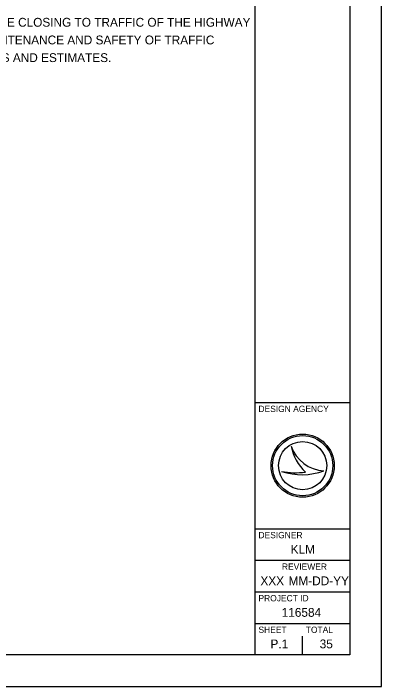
# Model space of a CAD drawing. Extents: x 0 to 34, y 0 to 22.
# Drawn here: x 28.17 to 34, y 0 to 10.67 of the extents above; entities that cross this region are included whole.
import ezdxf

# ---------------------------------------------------------------- set-up
doc = ezdxf.new("R2010")
doc.units = 0
for name, color, linetype in [('GM_X_County', 7, 'Continuous'), ('GM_X_Minor_Lake_Text', 7, 'Continuous'), ('GM_X_Minor_River_Text', 7, 'Continuous')]:
    doc.layers.add(name, color=color, linetype=linetype)

msp = doc.modelspace()

# ---------------------------------------------------------------- linework, layer by layer
at = {"layer": 'GM_X_County'}
msp.add_lwpolyline([(0, 0), (34, 0), (34, 22), (0, 22)], close=True, dxfattribs=at)
at = {"layer": 'GM_X_Minor_Lake_Text'}
for p, q in [((32.567, 3.81), (32.567, 3.81)), ((32.75, 3.5), (32.75, 3.5)), ((33.087, 3.419), (33.087, 3.419)), ((32.417, 3.41), (32.417, 3.41)), ((32.75, 0.5), (32.75, 0.8)), ((32.375, 0.675), (32.375, 0.675))]:
    msp.add_line(p, q, dxfattribs=at)
for radius in [0.5, 0.477, 0.477, 0.382]:
    msp.add_circle((32.75, 3.5), radius, dxfattribs=at)
for centre, radius, start, end in [((33.116, 3.998), 0.58, 198.9257, 198.9319), ((33.347, 3.97), 0.796, 191.6379, 191.6421), ((33.116, 3.998), 0.58, 198.9319, 267.1657), ((33.347, 3.97), 0.796, 191.6421, 226.0947), ((32.739, 4.37), 1.013, 251.4576, 290.0832), ((32.648, 4.654), 1.266, 259.4964, 259.4995), ((32.739, 4.37), 1.013, 251.4527, 251.4576), ((32.648, 4.654), 1.266, 259.4995, 276.6672)]:
    msp.add_arc(centre, radius, start, end, dxfattribs=at)
at = {"layer": 'GM_X_Minor_River_Text'}
for p, q in [((32, 0.5), (32, 21.5)), ((32, 4.5), (33.5, 4.5)), ((32, 2.5), (33.5, 2.5)), ((32, 2), (33.5, 2)), ((32, 1.5), (33.5, 1.5)), ((32, 1), (33.5, 1))]:
    msp.add_line(p, q, dxfattribs=at)
msp.add_lwpolyline([(1.5, 21.5), (33.5, 21.5), (33.5, 0.5), (1.5, 0.5)], close=True, dxfattribs=at)

# ---------------------------------------------------------------- texts
at = {"layer": 'GM_X_Minor_Lake_Text'}
for s, height, p in [('IMPROVEMENT WILL NOT REQUIRE THE CLOSING TO TRAFFIC OF THE HIGHWAY', 0.14, (24.528, 10.455)), ('AND THAT PROVISIONS FOR THE MAINTENANCE AND SAFETY OF TRAFFIC', 0.14, (24.528, 10.175)), ('WILL BE AS SET FORTH ON THE PLANS AND ESTIMATES.', 0.14, (24.528, 9.895)), ('DESIGN AGENCY', 0.1, (32.05, 4.35)), ('DESIGNER', 0.1, (32.05, 2.35)), ('KLM', 0.14, (32.561, 2.105)), ('REVIEWER', 0.1, (32.422, 1.85)), ('XXX', 0.14, (32.081, 1.605)), ('MM-DD-YY', 0.14, (32.527, 1.605)), ('PROJECT ID', 0.1, (32.05, 1.35)), ('116584', 0.14, (32.418, 1.105)), ('SHEET', 0.1, (32.05, 0.85)), ('TOTAL', 0.1, (32.8, 0.85)), ('35', 0.14, (33.02, 0.605)), ('P.1', 0.14, (32.24, 0.605))]:
    msp.add_text(s, height=height, dxfattribs=at).set_placement(p)

doc.saveas('drawing.dxf')
